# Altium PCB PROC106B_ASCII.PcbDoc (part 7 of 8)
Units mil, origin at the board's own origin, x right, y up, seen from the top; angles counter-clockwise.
Board outline 4498.18 x 1060.53 mil, 8 copper layers (Top Layer, GND1, Sig1, PWR1, PWR2, Sig2, GND2, Bottom Layer), stack 69.602 mil thick; 439 components, 327 nets, 1548 pads, 843 vias.
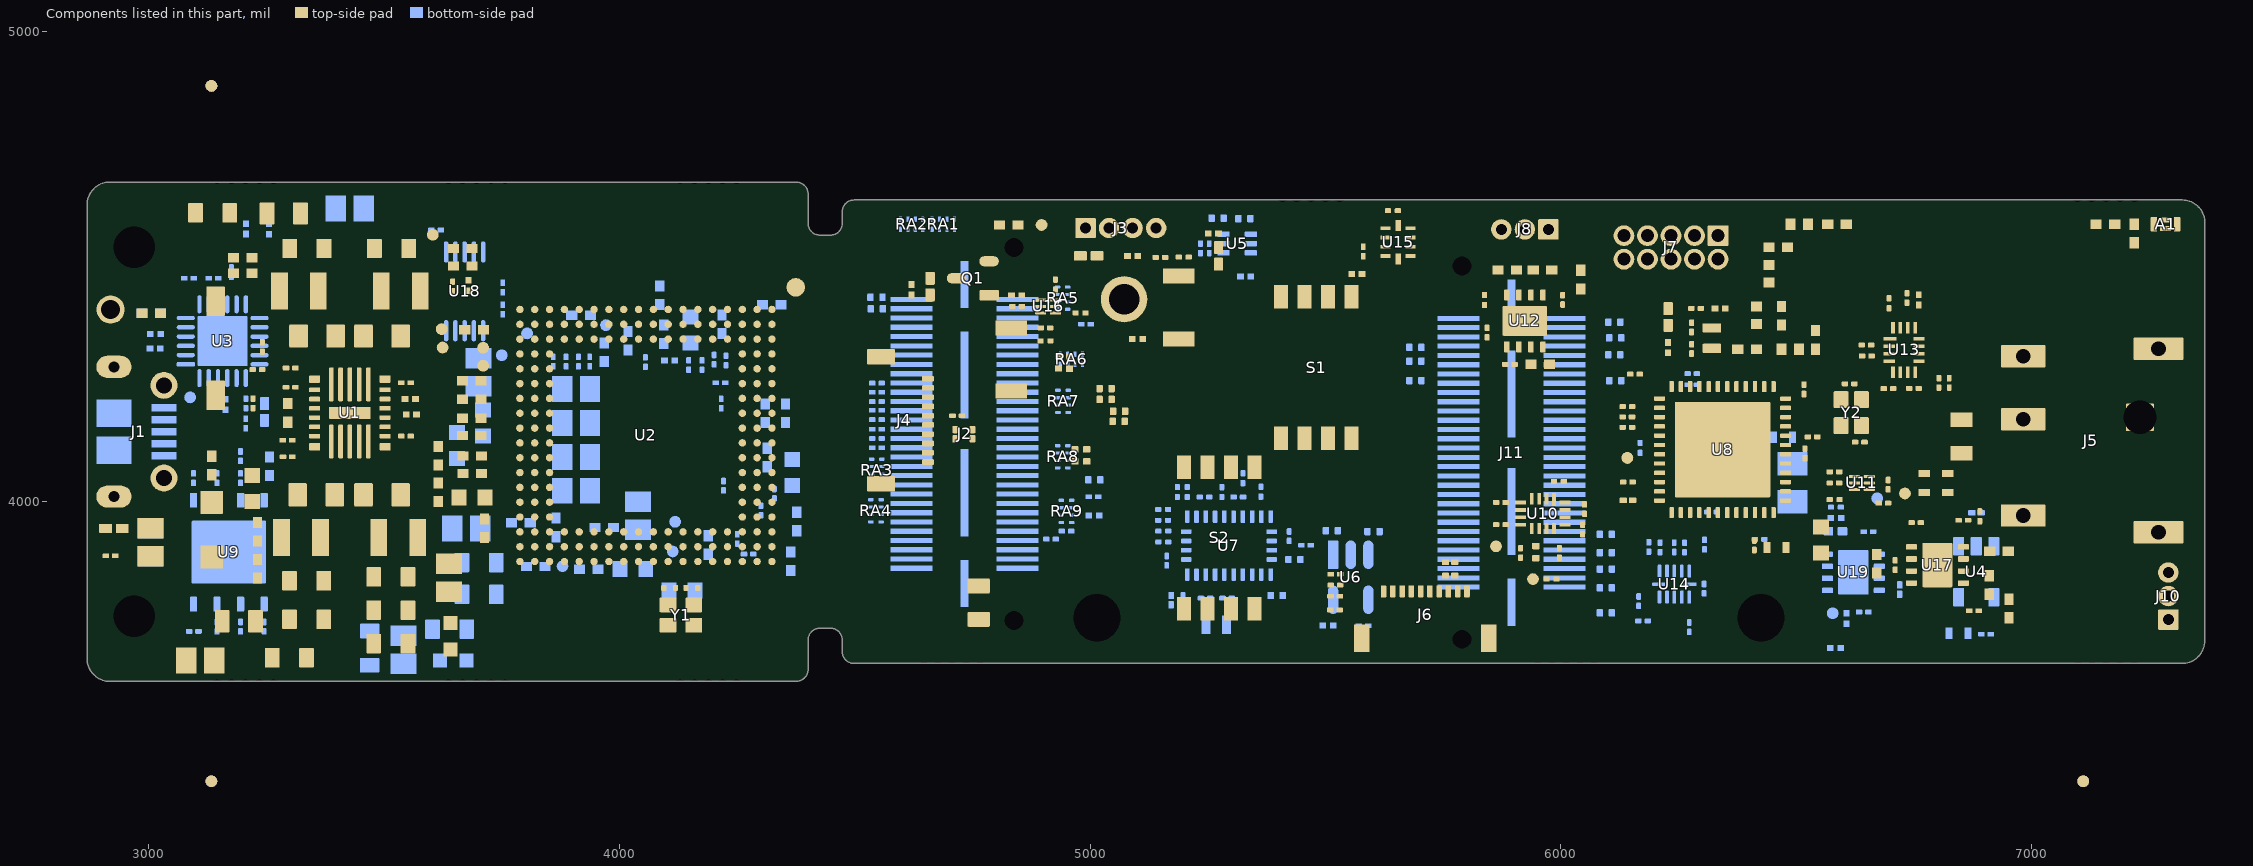
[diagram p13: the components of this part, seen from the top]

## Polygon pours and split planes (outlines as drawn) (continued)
GND on Bottom Layer "Bottom Layer-GND 3" (solid, remove dead copper, pour order 760): 3437.8,4669.84 3522.45,4669.84 3522.45,4586.72 3437.8,4586.72
GND on Bottom Layer "Bottom Layer-GND 5" (solid, remove dead copper, pour order 756): 3589.51,3885.19 3589.51,3816.34 3622.06,3783.79 3660.04,3745.8 3660.04,3708.73 3691.76,3708.73 3691.76,3893.86 3678.45,3907.17 3611.49,3907.17
GND on Bottom Layer "Bottom Layer-GND 2" (solid, remove dead copper, pour order 748): 3921.61,4124.36 3995.34,4124.36 3995.34,3981.19 3921.61,3981.19
AR_1P2 on Bottom Layer "Bottom Layer-AR_1P2" (solid, remove dead copper, pour order 742): 3283.69,4679.43 3417.05,4679.43 3417.05,4582.18 3283.69,4582.18
5V_IN on Bottom Layer "Bottom Layer-5V_IN" (solid, remove dead copper, pour order 721): 2969.58,3908.01 3085.96,3908.01 3085.96,3827.52 2969.58,3827.52
PMIC_1V0 on Bottom Layer "Bottom Layer-PMIC_1V0" (solid, remove dead copper, pour order 719): 3710.58,3701.2 3698.85,3689.47 3661.67,3689.47 3661.67,3629.17 3763.64,3629.17 3763.64,3701.2
no net on Bottom Layer "BOTTOM-No Net 1" (solid, remove dead copper, pour order 709): 3713.85,4118.01
no net on Bottom Layer "BOTTOM-No Net" (solid, pour order 707): 3795.02,4389.29
no net on Bottom Layer " " (solid, remove dead copper, pour order 705): 3587.57,4370.79
no net on Bottom Layer " " (solid, remove dead copper, pour order 703): 3587.57,4370.79
AR_1V8 on Bottom Layer "Bottom Layer-BB_1V8" (solid, remove dead copper, pour order 701): 3903.37,4272.45 3852.76,4272.45 3665,4272.45 3665,4219.16 3815.53,4219.16 3824.69,4210 3903.37,4210
AR_1V8 on Bottom Layer "BOTTOM-VCO_1V8" (solid, remove dead copper, pour order 697): 3975,3962.68 4012.22,3962.68 4071,3962.68 4071,3910.88 3975,3910.88
AR_1P0_RF1 on Bottom Layer "Bottom Layer-AR_1P0_RF1" (solid, remove dead copper, pour order 695): 3856.3,4159.48 3856.3,4197.12 3899.77,4197.12 3900.11,4131.96 3794.33,4131.96 3774.34,4131.96 3764.92,4122.55 3691.55,4122.54 3691.55,4159.48
AR_1V8 on Bottom Layer "BOTTOM-VCLK_1V8" (solid, remove dead copper, pour order 691): 3679.79,3911.04 3910.06,3911.04 3910.06,3943.24 3783.91,3943.24 3783.91,3983.65 3679.79,3983.65
no net on Bottom Layer "Bottom Layer-No Net" (solid, pour order 683): 3057.31,4083.94
PMIC_3V3 on Bottom Layer "Bottom Layer-PMIC_3V3" (solid, remove dead copper, pour order 681): 3004.01,4452.9 3113.51,4452.9 3113.51,4399.78 3109.47,4395.73 3102.51,4395.73 3097.94,4391.16 3097.94,4365.53 3051.98,4365.53 3033.61,4383.9 3004.01,4383.9
AR_1P0_RF1 on Bottom Layer "Bottom Layer-AR_1P0_RF1 1" (solid, remove dead copper, pour order 679): 3715.91,3777.88 3715.91,3726.32 3794.09,3726.32 3794.09,3828.85 3780.86,3842.09 3780.86,3896.41 3715.91,3896.41
5V_HD_IN on Bottom Layer "Bottom Layer-5V_HD_IN 1" (solid, pour order 557): 6641.93,3812.08 6641.93,3696.21 6707.53,3696.21 6707.53,3812.08 6702.57,3812.08 6659.82,3812.08 6662.84,3812.08
5V_HD_IN on Bottom Layer "Bottom Layer-5V_HD_IN 3" (solid, pour order 563): 4868.09,3859.51
5V_IN_B on Bottom Layer "Bottom Layer-5V_IN_B" (solid, pour order 521): 6653.01,3852.6 6759.98,3852.6 6759.98,4006.83 6775.86,4022.71 6798.1,4022.71 6798.1,4150.17 6690.11,4150.17 6690.11,4110.05 6690.85,4109.3 6690.85,4101.69 6690.85,4075.96 6690.86,4067.7 6655.23,4032.07 6655.23,3923.83 6657.56,3921.5 6658.81,3920.25 6675.91,3903.15 6685.85,3893.21 6685.75,3876.47 6681.98,3872.7 6653.01,3872.7
RE on Bottom Layer "Bottom Layer-RE" (solid, remove dead copper, pour order 505): 7331.54,4438.37 7307.92,4438.37 7307.92,4627.35 7331.54,4627.35
5V_IN on Bottom Layer "BOTTOM-5V_IN_SW" (solid, pour order 318): 6716.51,3843.31 6664.37,3843.31 6664.37,3827.48 6697.27,3827.48 6706.84,3817.91 6713.65,3817.91 6727.01,3817.91 6727.01,3728.16 6799.26,3728.16 6826.37,3755.28 6826.37,3800.18 6821.37,3805.18 6801.37,3805.18 6782.49,3805.18 6777.74,3809.92 6777.74,3842.18 6773.37,3846.18 6719.37,3846.18
no net on Bottom Layer " " (solid, remove dead copper, pour order 459): 4514.15,4464.37
no net on Bottom Layer "BOTTOM-No Net 3" (solid, pour order 266): 4918.91,3816.49
no net on Bottom Layer "BOTTOM-No Net 4" (solid, pour order 264): 4983.76,3878.78
AR_1P0_RF1 on PWR1 "PWR1-AR_1P0_RF1" (solid, remove dead copper, pour order 725): 3696.4,3846.98 3714.8,3828.66 3783.45,3828.66 3783.45,3726.14 3520.23,3726.14 3520.23,3982.24 3689.65,4151.66 3872.58,4151.66 3872.58,4038.59 3731.51,4038.59 3696.4,4003.44
AR_1P2 on PWR1 "PWR1-AR_1P2" (solid, remove dead copper, pour order 731): 4383.81,4173.3 4383.81,4319.42 4383.81,4679.43 3769.2,4679.43 3254.72,4679.43 3254.72,4485.55 3606.66,4485.55 3606.66,4349.35 3935.57,4349.35 3935.57,4419.55 4276.95,4419.55 4302.94,4393.56 4302.94,4179.48 4325.05,4157.06 4325.05,4115.19 4335.64,4104.6 4335.64,3889.16 4152.76,3889.16 4152.76,3822.45 4383.81,3822.45 4383.81,4093.23
AR_1V8 on PWR1 "PWR1-AR_1V8" (solid, remove dead copper, pour order 723): 4317.82,4156.75 4296.2,4178.37 4296.2,4372.39 4266.03,4403.13 3952.06,4403.13 3910.52,4361.6 3660.28,4361.6 3593.74,4295.06 3322.56,4294.82 3322.56,3824.21 3281.64,3783.2 3142.74,3783.2 3142.74,3618.01 3500.96,3618.01 3500.96,3997.33 3676.25,4172.62 3923.29,4172.62 3923.29,4273.48 4199.1,4273.48 4199.1,4021.86 4199.1,4020.83 4184.31,4005.54 3744.04,4005.54 3729.16,3990.66 3729.26,3874.14 3749.49,3853.9 3750.27,3853.73 3989.56,3853.73 4046.2,3910.37 4317.82,3910.37
PMIC_1V0 on PWR1 "PWR1-PMIC_1V0" (solid, remove dead copper, pour order 864): 3679.96,3619.99 3679.96,3702.53 3774.68,3702.53 3774.68,3619.99
5V_IN on PWR1 "PWR1-5V_IN 1" (solid, remove dead copper, pour order 804): 6141.87,4641.38 7225.46,4641.38 7225.46,4357.95 7367.49,4358.05 7367.49,3676.33 6736.31,3676.33 6736.31,3926.82 6479.48,4183.28 5319.35,4183.28 4687.15,4183.28 4621.42,4117.56 4621.33,3669.11 4525.19,3669.11 4484.07,3669.11 4484.07,3849.59 4504.63,3849.59 4525.19,3864.58 4525.19,4641.38 5562.04,4641.38
5V_HD_IN on PWR1 "PWR1-5V_HD_IN" (solid, remove dead copper, pour order 366): 4635.53,4107.41 4635.53,3657.14 4801.12,3657.14 6712,3657.14 6712,3928.7 6480.61,4160.09 4688.21,4160.09
GND on PWR1 "PWR1-GND" (solid, remove dead copper, pour order 820): 3962.57,4259.22 3962.51,4259.86 4180.36,4259.86 4180.36,4031.23 3955.54,4031.23 3955.54,4259.22
5V_IN on PWR1 "PWR1-5V_IN" (solid, remove dead copper, pour order 734): 3300,3843.45 3252.31,3795.76 3252.31,3795.43 3073.61,3795.43 3073.61,3588.77 2869.58,3588.77 2869.58,4710.9 3245.35,4710.9 3245.35,4475.15 3587.25,4475.15 3587.25,4312.5 3300,4312.5
no net on PWR1 "L4 PWR/GND-No Net" (solid, pour order 380): 3990.62,4017.94
GND on Sig1 "      " (solid, remove dead copper, pour order 850): 2828.55,3502.51 4359.83,3502.51 4359.83,3540.49 7326.73,3540.49 7326.73,4241.62 7189.18,4241.62 7189.18,4455.67 7189.2,4491.21 7189.18,4525 4359.83,4525 4359.83,4563.04 2828.55,4563.04
GND on Sig1 "      " (solid, pour order 848): 7230.23,4607.59
3V0 on Sig1 "Sig1-3V0" (solid, remove dead copper, pour order 422): 5446.44,3648.08 5446.44,3740.77 5595.34,3889.68 5748.5,3889.68 5802.08,3836.09 5802.08,3784.14 5860.53,3725.69 6169.64,3725.69 6235.53,3789.89 6235.53,3854.82 6235.53,3991.13 6627.54,3991.13 6738.96,3879.71 6738.96,3854.82 6817.4,3854.82 6844.28,3827.94 6844.28,3688.85 6676.2,3688.85 6676.2,3872.61 6372.91,3872.61 6372.91,3648.08
no net on Sig1 "Sig1-No Net" (solid, remove dead copper, pour order 740): 4088.43,4371.99
no net on Sig1 "L3 SIG 1-No Net" (solid, pour order 511): 3904.98,4012.92
GND on GND1 "GND1-GND" (solid, remove dead copper, pour order 358): 4400.86,4641.38 4400.86,4683.33 2896.63,4683.34 2866.42,4653.12 2866.42,3646.93 2901.93,3611.42 2908,3617.49 4400.86,3617.49 4400.86,3656.87 7367.49,3656.87 7367.49,4358 7230.09,4358 7230.25,4641.38
no net on GND1 "L6 SIG 2-No Net" (solid, pour order 302): 4825.92,3926.28
no net on GND1 "DVDD_21MP_1V8_L08_P-001" (solid, remove dead copper, pour order 300): 3885.7,4301.32
PMIC_3V3 on PWR2 "PWR2-PMIC_3V3" (solid, remove dead copper, pour order 487): 4615.73,4308.97 4816.08,4509.31 4816.08,4512.23 4816.08,4631.43 4498.89,4631.43 4400.86,4631.43 4400.86,4710.69 2869.58,4710.9 2869.58,3586.35 4376.76,3586.35 4376.76,3820.05 4376.76,4308.97 4415.39,4308.97
VCC_BA_3V3 on PWR2 "PWR2-VCC_BA_3V3" (solid, remove dead copper, pour order 738): 4794.48,4263.72 4759.59,4298.61 4759.59,4414.21 4838.48,4493.1 4838.48,4641.38 7229.32,4641.38 7229.31,4358 7367.49,4358 7367.49,3657.14 4794.48,3657.14
5V_IN on PWR2 " " (solid, remove dead copper, pour order 485): 3880.16,4286.09 3848.77,4254.7 3706.1,4254.7 3706.1,4223.31 3664.77,4181.97 3492.6,4181.97 3492.6,4313.97 3583.8,4313.97 3584.11,4493.43 3259.65,4493.43 3259.65,3889.51 4016.31,3889.51 4108.84,3982.04 4306.6,3982.03 4322,3966.64 4322,3920.77 4353.26,3889.51 4413.43,3889.51 4439.46,3863.48 4453.67,3863 4483.91,3863 4485.31,3861.61 4485.31,3661.8 4490.12,3656.98 4514.15,3656.87 4748.59,3656.87 4748.59,3887.85 4748.59,4286.09
VDDS on PWR2 "PWR2-VDDS" (solid, remove dead copper, pour order 404): 6492.17,3939.96 6492.17,4039.29 6539.41,4086.52 6582.96,4086.52 6582.96,4179.9 6582.31,4179.25 6460.14,4179.25 6427.22,4212.17 6283.81,4212.17 6200.92,4295.06 6134.69,4295.06 6134.69,4010.53 6208.12,3939.96
no net on PWR2 " " (solid, remove dead copper, pour order 406): 3419.66,3877.85
no net on Bottom Solder (solid): 4400.86,4518.08 3736.09,4518.08 3736.09,4678.67 4400.86,4678.67
no net on Bottom Solder (solid): 3815.62,3618.33 3815.62,3780.33 4400.86,3780.33 4400.86,3634.41 4384.78,3618.33
no net on Bottom Solder (solid): 4189.03,4266.74 4189.03,4031.3 4008.5,4031.3 4008.5,4266.74
no net on Bottom Solder " " (solid, remove dead copper): 4514.15,4464.37
no net on Bottom Solder " " (solid, remove dead copper): 4512,4464.37
no net on M1 Board Outline " " (solid, remove dead copper): 3143.52,4361.87
no net on M1 Board Outline " " (solid, remove dead copper): 3145.55,4361.06
no net on Top Paste " " (solid): 4029.26,4016.78 3910.77,4016.78 3910.77,4130.21 4029.26,4130.21
no net on Top Paste " " (solid): 4169.12,4155.98 4050.63,4155.98 4050.63,4269.41 4169.12,4269.41
no net on Top Paste " " (solid): 4169.12,4016.78 4050.63,4016.78 4050.63,4130.21 4169.12,4130.21
no net on Top Paste " " (solid): 4029.26,4155.98 3910.77,4155.98 3910.77,4269.41 4029.26,4269.41
no net on Top Solder " " (solid): 4169.12,4016.78 4050.63,4016.78 4050.63,4130.21 4169.12,4130.21
no net on Top Solder " " (solid): 4169.12,4155.98 4050.63,4155.98 4050.63,4269.41 4169.12,4269.41
no net on Top Solder " " (solid): 4029.26,4016.78 3910.77,4016.78 3910.77,4130.21 4029.26,4130.21
no net on Top Solder " " (solid): 4029.26,4155.98 3910.77,4155.98 3910.77,4269.41 4029.26,4269.41
GND on GND2 "GND 3-GND" (solid, remove dead copper, pour order 310): 4438.86,3618.9 7367.49,3614.6 7367.49,4358 7230.24,4358 7230.24,4686.41 4522.77,4686.41 2869.56,4686.41 2869.85,3618.9
GND on Sig2 "      " (solid, remove dead copper, pour order 854): 2869.58,3618.9 4400.86,3618.9 4400.86,3656.87 4400.86,3731.52 4473.63,3731.52 4473.63,3657.18 4474.07,3656.87 7367.49,3656.87 7367.49,4358 7228.97,4358 7228.97,4572.06 7228.97,4607.59 7228.97,4641.38 4400.86,4641.38 4400.86,4679.43 2869.58,4679.43

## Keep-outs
Bottom Layer:
  rectangle: 3813.97,3824.21 4076.76,3834.25
Keep-Out Layer:
  circle w1: c5014.62,3754.06 r118.11
  circle w1: c6425.96,3754.06 r118.11
  text ".Layer_Name" at 577,-858.49 h60

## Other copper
Top Layer:
  text ".Layer_Name" at 577,-858.49 h60
GND1:
  text ".Layer_Name" at 577,-858.49 h60
Sig1:
  text ".Layer_Name" at 577,-858.49 h60
PWR1:
  text ".Layer_Name" at 577,-858.49 h60
PWR2:
  text ".Layer_Name" at 577,-858.49 h60
Sig2:
  text ".Layer_Name" at 577,-858.49 h60
GND2:
  text ".Layer_Name" at 577,-858.49 h60
Bottom Layer:
  text ".Layer_Name" at 577,-858.49 h60

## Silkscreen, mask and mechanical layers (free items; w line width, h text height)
Top Overlay:
  drawing of 931 lines, arcs and shapes, not listed
  text "ANT" at 7247.11,4618.46 h15
  text "3V3" at 4971.03,4609.77 h15
  text "SCL" at 5026.44,4609.1 h15
  text "SDA" at 5075.13,4609.42 h15
  text "GND" at 5132,4609 h15
  text "CAN1" at 5705.55,4605.09 h15
  text "3V3" at 3575.93,4600.61 h15
  text "CAN_L" at 6013.93,4563.4 h15
  text "CAN_H" at 5772.29,4557.35 h15
  text "GND" at 5902.73,4526.81 h15
  text "60PIN" at 5461.3,4505.87 h15 r90
  text "60PIN/BT" at 5407.96,4487.66 h15 r90
  text "3V3" at 4942.95,4473.45 h15
  text "LED" at 4995.38,4473.19 h15
  text "BT_JTAG_HDR" at 6201.8,4466.71 h15
  text "USR_LED" at 5256.55,4450.34 h13
  text "PROC106B" at 6836.63,4404.24 h25
  text "RST_LED" at 4614,4391 h15
  text "REV. B" at 6899.9,4369.83 h25
  text "GND" at 5054.02,4359.61 h15
  text "GND" at 2907.55,4353.02 h15
  text "BT_LED" at 6186.99,4348.24 h15 r90
  text "S3" at 3013.35,4323.17 h25
  text "USR_SW" at 5152.14,4301.5 h15
  text "SOP2" at 2999.29,4296.66 h15
  text "RST_SW" at 4794.22,4190.93 h15
  text "CAN" at 5202.96,4125.61 h15 r90
  text "60PIN" at 5257.16,4116.94 h15 r90
  text "BT_EN" at 5300.52,4106.1 h15 r90
  text "PROC106B" at 2866.22,4100.51 h25
  text "REV. B" at 2897.63,4071.86 h25
  text "BT" at 5464.69,4051.28 h15 r90
  text "SOP0" at 5511.87,4024.99 h15 r90
  text "SOP1" at 5563.64,4022.15 h15 r90
  text "CP2105" at 5431.33,4007.09 h15 r90
  text "5V_LED" at 2974.55,3984.77 h15
  text "LCD_DISP2" at 4737,3978 h15 r90
  text "5V, 2A" at 7023.94,3880.64 h25
  text "CAN_H" at 7195.3,3876.22 h15
  text "LCD_DISP1" at 5564.31,3865.44 h15
  text "GND" at 7243.19,3786.08 h15 r90
  text "CAN2" at 7119,3761 h25
  text "CAN_L" at 7189,3721 h15
  text "BT_DIS" at 5331.39,3700.83 h15
  text "BT/LCD" at 5214.43,3697.87 h15
  text "SPI" at 5198.89,3696.39 h15 r90
  text ".Layer_Name" at 557.88,-855.15 h60
Bottom Overlay:
  lines w6: 3076.75,4275.09 3064.53,4275.09 3077.44,4262.17 3077.44,4274.39 ; 3742.27,4351.32 3750.91,4342.68 3750.91,4360.94 3742.27,4352.3 ; 4566.51,3859.44 4557.87,3850.8 4557.87,3869.06 4566.51,3860.42 ; 5190.34,3835.05 5178.12,3835.05 5191.04,3822.14 5191.04,3834.36 ; 5366.68,4568.32 5375.32,4559.68 5375.32,4577.94 5366.68,4569.3 ; 5498.49,3885.48 5489.85,3876.84 5489.85,3895.1 5498.49,3886.46 ; 6061.18,4387.35 6069.82,4378.71 6069.82,4396.98 6061.18,4388.34 ; 6286.44,3772.48 6277.8,3763.84 6296.07,3763.84 6287.43,3772.48 ; 6545.92,3811.92 6537.28,3803.28 6537.28,3821.55 6545.92,3812.91 ; 6822.27,3908.34 6813.62,3899.69 6813.62,3917.96 6822.27,3909.32
  lines w7.64: 3376.95,4259.36 3435.38,4360.56 3493.81,4259.36 3376.95,4259.36
  text "S/N:" at 7054.26,4555.33 h40
  text "J11" at 5720.69,4441.63 h25
  text "OPN:" at 7053.04,4398.05 h40
  text "For evaluation only;" at 6904.33,4270.31 h30
  text "not FCC approved for resale." at 6905.33,4220.31 h30
  text "USB_LED" at 3294.77,4133.76 h15 r270
  text "ICBOOST_CONN" at 5046.93,4070.06 h25 r270
  text "DCA_CONN" at 5658.79,4014.25 h25 r270
  text "USB1" at 2938.13,3956.53 h15
  text "U14" at 6365,3859 h25
  text ".Layer_Name" at 577,-858.49 h60
Top Paste:
  text ".Layer_Name" at 577,-858.49 h60
Bottom Paste:
  text ".Layer_Name" at 577,-858.49 h60
Top Solder:
  text ".Layer_Name" at 577,-858.49 h60
  text ".Layer_Name" at 577,-858.49 h60
Bottom Solder:
  text ".Layer_Name" at 577,-858.49 h60
Drill Guide:
  text ".Layer_Name" at 577,-858.49 h60
M1 Board Outline:
  lines w1: 2917.58,3586.87 2917.58,3586.87
  lines w6: 3043.52,4771.95 2893.99,4771.95 ; 4408.74,4993.07 7334.57,4993.07 ; 5242.82,4819.03 cw(c5242.82,4776.51) 5285.34,4776.51 ccw(c5327.85,4776.51) 5327.85,4734 5349.85,4734 ; 5242.82,4819.16 4924.89,4819.16 ccw(c4924.89,4776.65) 4882.38,4776.65 cw(c4839.86,4776.65) 4839.86,4734.13 4405.8,4734.13 cw(c4405.8,4743.59) 4396.34,4743.59 4396.34,4758.92 ccw(c4383.31,4758.92) 4383.31,4771.95 2893.99,4771.95 ; 5631,4734 5670.37,4734 ccw(c5670.37,4776.51) 5712.88,4776.51 cw(c5755.4,4776.51) 5755.4,4819.03 cw(c5755.57,4819.03) 5755.57,4819.2 6393.01,4819.2 cw(c6393.01,4776.68) 6435.53,4776.68 ccw(c6478.04,4776.68) 6478.04,4734.17 ; 6478.04,4733.95 7319.76,4733.95 ccw(c7319.57,4733.95) 7319.57,4734.13 7320.05,4734.13 ; 6824.41,4993.07 2895.02,4993.07 ccw(c2895.02,4967.63) 2869.59,4967.63 2869.59,4796.35 ccw(c2893.99,4796.35) 2893.99,4771.95 ; 7317.76,4993.07 cw(c7317.76,4943.07) 7367.76,4943.07 7367.76,4781.58 cw(c7320.31,4781.58) 7320.31,4734.13 ; 7320.59,3563.53 4607.03,3563.53 4428.96,3563.53 ccw(c4428.96,3550.55) 4415.97,3550.55 4415.97,3537.53 cw(c4404.81,3537.53) 4404.81,3526.38 3043.52,3526.38 2923.72,3526.38 2907.56,3526.38 ccw(c2907.56,3488.4) 2869.58,3488.4 2869.58,3349.31 ccw(c2912.09,3349.31) 2912.09,3306.8 6841.48,3306.8 7329.95,3306.8 ccw(c7329.95,3343.5) 7366.66,3343.5 ; 7321.69,3563.53 cw(c7321.69,3517.44) 7367.79,3517.44 ; 7367.76,3343.5 7367.76,3517.41
  lines w10: 2869.58,3666.9 ccw(c2917.58,3666.9) 2917.58,3618.9 ; 2869.58,3666.9 ccw(c2917.58,3666.9) 2917.58,3618.9 ; 2869.58,3666.9 2869.58,4631.43 ; 2869.58,3666.9 2869.58,4631.43 ; 2869.58,4631.43 cw(c2917.58,4631.43) 2917.58,4679.43 ; 2869.58,4631.43 cw(c2917.58,4631.43) 2917.58,4679.43 ; 2917.58,3618.9 4375.86,3618.9 2917.58,3618.9 ; 2917.58,4679.43 4375.28,4679.43 2917.58,4679.43 ; 4400.86,3644 cw(c4375.86,3644) 4375.86,3619 ccw(c4375.86,3644) 4400.86,3644 ; 4400.86,3644 4400.86,3706.52 ; 4400.86,3644 4400.86,3706.52 ; 4400.86,3706.52 cw(c4425.86,3706.52) 4425.86,3731.52 ; 4400.86,3706.52 cw(c4425.86,3706.52) 4425.86,3731.52 ; 4400.86,3876.17 ccw(c4425.86,3876.17) 4425.86,3851.17 ; 4400.86,3876.17 ccw(c4425.86,3876.17) 4425.86,3851.17 ; 4400.86,3876.17 4400.86,3900.82 ; 4400.86,3876.17 4400.86,3900.82 ; 4400.86,3900.82 cw(c4425.86,3900.82) 4425.86,3925.82 ; 4400.86,3900.82 cw(c4425.86,3900.82) 4425.86,3925.82 ; 4400.86,4136.81 ccw(c4425.86,4136.81) 4425.86,4111.81 ; 4400.86,4136.81 ccw(c4425.86,4136.81) 4425.86,4111.81 ; 4400.86,4136.81 4400.86,4161.47 ; 4400.86,4136.81 4400.86,4161.47 ; 4400.86,4161.47 cw(c4425.86,4161.47) 4425.86,4186.47 ; 4400.86,4161.47 cw(c4425.86,4161.47) 4425.86,4186.47 ; 4400.86,4397.47 ccw(c4425.86,4397.47) 4425.86,4372.47 ; 4400.86,4397.47 ccw(c4425.86,4397.47) 4425.86,4372.47 ; 4400.86,4397.47 4400.86,4422.12 ; 4400.86,4397.47 4400.86,4422.12 ; 4400.86,4422.12 cw(c4425.86,4422.12) 4425.86,4447.12 ; 4400.86,4422.12 cw(c4425.86,4422.12) 4425.86,4447.12 ; 4400.86,4591.77 ccw(c4425.86,4591.77) 4425.86,4566.77 ; 4400.86,4591.77 ccw(c4425.86,4591.77) 4425.86,4566.77 ; 4400.86,4591.77 4400.86,4654.3 ; 4400.86,4591.77 4400.86,4654.3 ; 4400.86,4654.3 ccw(c4375.86,4654.3) 4375.86,4679.3 cw(c4375.86,4654.3) 4400.86,4654.3 ; 4425.86,3731.52 4448.63,3731.52 ; 4425.86,3731.52 4448.63,3731.52 ; 4425.86,3851.17 4448.63,3851.17 ; 4425.86,3851.17 4448.63,3851.17 ; 4425.86,3925.82 4448.63,3925.82 ; 4425.86,3925.82 4448.63,3925.82 ; 4425.86,4111.81 4448.63,4111.81 ; 4425.86,4111.81 4448.63,4111.81 ; 4425.86,4186.47 4448.63,4186.47 ; 4425.86,4186.47 4448.63,4186.47 ; 4425.86,4372.47 4448.63,4372.47 ; 4425.86,4372.47 4448.63,4372.47 ; 4425.86,4447.12 4448.63,4447.12 ; 4425.86,4447.12 4448.63,4447.12 ; 4425.86,4566.77 4448.63,4566.77 ; 4425.86,4566.77 4448.63,4566.77 ; 4448.63,3731.52 cw(c4448.63,3706.52) 4473.63,3706.52 ; 4448.63,3731.52 cw(c4448.63,3706.52) 4473.63,3706.52 ; 4448.63,3851.17 ccw(c4448.63,3876.17) 4473.63,3876.17 ; 4448.63,3851.17 ccw(c4448.63,3876.17) 4473.63,3876.17 ; 4448.63,3925.82 cw(c4448.63,3900.82) 4473.63,3900.82 ; 4448.63,3925.82 cw(c4448.63,3900.82) 4473.63,3900.82 ; 4448.63,4111.81 ccw(c4448.63,4136.81) 4473.63,4136.81 ; 4448.63,4111.81 ccw(c4448.63,4136.81) 4473.63,4136.81 ; 4448.63,4186.47 cw(c4448.63,4161.47) 4473.63,4161.47 ; 4448.63,4186.47 cw(c4448.63,4161.47) 4473.63,4161.47 ; 4448.63,4372.47 ccw(c4448.63,4397.47) 4473.63,4397.47 ; 4448.63,4372.47 ccw(c4448.63,4397.47) 4473.63,4397.47 ; 4448.63,4447.12 cw(c4448.63,4422.12) 4473.63,4422.12 ; 4448.63,4447.12 cw(c4448.63,4422.12) 4473.63,4422.12 ; 4448.63,4566.77 ccw(c4448.63,4591.77) 4473.63,4591.77 ; 4448.63,4566.77 ccw(c4448.63,4591.77) 4473.63,4591.77 ; 4473.47,4616.39 cw(c4498.47,4616.39) 4498.47,4641.39 ccw(c4498.47,4616.39) 4473.47,4616.39 ; 4473.47,4616.39 4473.63,4591.77 ; 4473.47,4616.39 4473.63,4591.77 ; 4473.63,3706.52 4473.63,3681.91 4473.63,3706.52 ; 4473.63,3876.17 4473.63,3900.82 ; 4473.63,3876.17 4473.63,3900.82 ; 4473.63,4136.81 4473.63,4161.47 ; 4473.63,4136.81 4473.63,4161.47 ; 4473.63,4397.47 4473.63,4422.12 ; 4473.63,4397.47 4473.63,4422.12 ; 7319.76,4641.43 cw(c7319.76,4593.44) 7367.75,4593.44 ; 7319.76,4641.43 cw(c7319.76,4593.44) 7367.75,4593.44 ; 7319.76,4641.43 4498.47,4641.43 7319.76,4641.43 ; 7367.76,3704.87 cw(c7319.76,3704.87) 7319.76,3656.87 ccw(c7319.76,3704.87) 7367.76,3704.87 ; 7367.76,3704.87 7367.76,4593.44 ; 7367.76,3704.87 7367.76,4593.44 ; 7367.75,4593.44 7367.76,4593.44 ; 7367.75,4593.44 7367.76,4593.44 ; 4473.47,3681.91 ccw(c4498.47,3681.91) 4498.47,3656.91 cw(c4498.47,3681.91) 4473.47,3681.91 ; 4498.47,3656.87 7319.49,3656.87 4498.47,3656.87
  text "M1 Board Outline" at 577,-858.49 h60
M2 Board Dimensions:
  text "X3" at 4305,3996 h60 r90
  text "X3" at 4837,3440 h60
  text "M2 Board Dimensions" at 577,-858.49 h60
M3 3D STEP Top:
  text ".Layer_Name" at 577,-858.49 h60
M4 3D STEP Bottom:
  text ".Layer_Name" at 577,-858.49 h60
M5 Assembly Top:
  lines w2: 3900.18,4006.48 3900.18,4279.71 4179.71,4279.71 4179.71,4006.48 3900.18,4006.48
  lines w6: 3737.37,3862.55 3745.19,3854.73 3745.92,3854.73 ; 3745.92,4221.46 3745.92,3854.73 ; 3752.8,3861.61 3745.92,3854.73 ; 4662.01,4263.83 4670.65,4255.19 4670.65,4273.46 4662.01,4264.82 4662.01,4263.83 ; 4783.42,4428.97 4783.42,4429.96 4792.06,4438.6 4792.06,4420.33 4783.42,4428.97 ; 4938.22,4398.63 4938.22,4399.62 4946.86,4408.26 4946.86,4389.99 4938.22,4398.63 ; 5551.38,3777.7 5560.02,3786.34 5560.02,3787.32 5551.38,3795.97 5551.38,3777.7 ; 5966.42,4578.64 5975.06,4587.28 5976.04,4587.28 5984.68,4578.64 5966.42,4578.64 ; 6328.53,4574.58 6337.17,4583.22 6338.16,4583.22 6346.8,4574.58 6328.53,4574.58 ; 7291.94,3711.22 7291.94,3729.48 7300.58,3720.84 7300.58,3719.86 7291.94,3711.22
  lines w10: -287.5,-917.17 6312.5,-917.17 ; -287.5,-713.83 6314.5,-713.83 ; -287.5,-510.5 -287.5,-1120.5 3717.5,-1120.5 6314.5,-1120.5 6314.5,-510.5 -287,-510.5 -287,-1120.5 1288.5,-1120.5 ; 2177.5,-1120.5 2177.5,-510.5 ; 3444.5,-713.83 3444.5,-510.5 ; 4284.5,-713.83 4284.5,-510.5 ; 4906.5,-1127 4906.5,-924.17
  text "COMPONENTS MARKED 'DNP' SHOULD NOT BE POPULATED." at -159.85,-299.74 h60
  text "ASSEMBLY VARIANT:" at -160.35,-415.24 h60
  text ".VariantName" at 875.65,-415.24 h60
  text "PCB VIEWED FROM TOP SIDE" at -228.5,-655.67 h60
  text "BOARD #:" at 2248,-655.67 h60
  text ".PRJ_Number" at 2793.5,-655.67 h60
  text "REV:" at 3638,-655.67 h60
  text ".PCB_Rev" at 3929.5,-655.67 h60
  text "SVN REV:" at 4476,-655.67 h60
  text ".VersionControl_RevNumber" at 4982,-655.67 h60
  text ".Layer_Name" at 538.89,-854.26 h60
  text "TID #:" at 2248,-859 h60
  text ".TID" at 2793.5,-859 h60
  text "PLOT NAME =" at -228.5,-1064.34 h60
  text ".plot_File_Name" at 577,-1064.34 h60
  text "GENERATED    :" at 2250,-1064.34 h60
  text ".Print_Date" at 3119.5,-1064.34 h60
  text ".Print_Time" at 3848.5,-1064.34 h60
  text "TEXAS INSTRUMENTS" at 5113,-1064.34 h60
M6 Assembly Bottom:
  lines w6: 3051.59,4095.56 3060.23,4086.92 3060.23,4105.18 3051.59,4096.54 ; 3056.52,4289.78 3047.88,4281.14 3047.88,4299.4 3056.52,4290.76 ; 4556.9,3856.76 4548.26,3848.12 4548.26,3866.39 4556.9,3857.74 ; 6054.41,4389.59 6063.05,4380.95 6063.05,4399.22 6054.41,4390.57
  lines w10: -288,-714.33 6314,-714.33 ; -286,-917.67 6314,-917.67 ; 1120,-1127.5 1120,-924.67 ; 1742,-714.33 1742,-511 ; 2582,-714.33 2582,-511 ; 3849,-1121 3849,-511 ; 4510.26,4292.38 4510.26,4160.86 ; 4518.19,4168.91 4510.26,4160.98 4510.26,4160.86 ; 4738,-1121 6313.5,-1121 6313.5,-511 -288,-511 -288,-1121 2309,-1121 6314,-1121 6314,-511 ; 4510.26,4160.86 4501.64,4169.48 4510.26,4160.86
  text "COMPONENTS MARKED 'DNP' SHOULD NOT BE POPULATED." at 6102,-318 h60
  text ".VariantName" at 5058,-434 h60
  text "ASSEMBLY VARIANT:" at 6097,-434 h60
  text ".VersionControl_RevNumber" at 1035.5,-656.17 h60
  text "SVN REV:" at 1541.5,-656.17 h60
  text ".PCB_Rev" at 2088,-656.17 h60
  text "REV:" at 2379.5,-656.17 h60
  text ".PRJ_Number" at 3224,-656.17 h60
  text "BOARD #:" at 3769.5,-656.17 h60
  text "PCB VIEWED FROM BOTTOM SIDE" at 6246,-656.17 h60
  text ".Layer_Name" at 1514.22,-848.89 h60
  text ".TID" at 3224,-859.5 h60
  text "TID #:" at 3769.5,-859.5 h60
  text "TEXAS INSTRUMENTS" at 904.5,-1064.84 h60
  text ".Print_Time" at 2169,-1064.84 h60
  text ".Print_Date" at 2898,-1064.84 h60
  text "GENERATED    :" at 3767.5,-1064.84 h60
  text ".plot_File_Name" at 5440.5,-1064.84 h60
  text "PLOT NAME =" at 6246,-1064.84 h60
M10 Fab Notes:
  drawing of 254 lines, arcs and shapes, not listed
  text "2" at 3215,8061 h70
  text "1" at 739.84,8036.5 h70
  text "3" at 5724.84,8036.5 h70
  text "4" at 8231.51,8036.5 h70
  text "5" at 10730.5,8036.5 h70
  text "6" at 13235.5,8036.5 h70
  text "A" at -416.5,6893.5 h70
  text "A" at 14383.5,6893.5 h70
  text "DESIGN INFORMATION" at 12391.15,6364.21 h60
  text "4" at 12769.13,6238.04 h60
  text "MIN. TRACK WIDTH:" at 11746.59,6232.09 h60
  text "MIL" at 12997.59,6232.09 h60
  text "MIN. CLEARANCE:" at 11746.59,6107.96 h60
  text "4" at 12782.83,6107.96 h60
  text "MIL" at 12997.59,6107.96 h60
  text "MIN. VIA PAD SIZE:" at 11746.59,5983.83 h60
  text "18" at 12812.84,5983.84 h60
  text "MIL" at 12997.59,5983.83 h60
  text "0.05mm (2MIL)" at 12441.59,5853.93 h60
  text "MINIMUM ANNULAR RING" at 11417.36,5845.71 h60
  text "EXTERNAL" at 13149.59,5845.71 h60
  text "PER" at 11617.36,5735.58 h60
  text "IPC-D-275 CLASS 2 LEVEL C" at 11837.36,5735.58 h60
  text "MIL, HOLES" at 13325.59,5635.11 h60
  text "+/-" at 12933.13,5626.52 h60
  text "+/-" at 13787.13,5626.52 h60
  text "REGISTRATION TOLERANCES:" at 11417.36,5625.46 h60
  text "METAL" at 12617.13,5625.46 h60
  text "5" at 13193.33,5625.46 h60
  text "3" at 14026.33,5625.46 h60
  text "MIL" at 14142.59,5625.46 h60
  text "HOLE SIZE TOLERANCE (UNLESS OTHERWISE SPECIFIED):" at 11417.36,5527.14 h60
  text "+/-" at 13787.13,5524.27 h60
  text "3" at 14026.33,5523.21 h60
  text "MIL" at 14142.59,5523.2 h60
  text "MATERIAL:" at 11342.59,5385.56 h60
  text "FR-4 High Tg" at 12329.03,5257.03 h60
  text "X" at 12176.59,5254.04 h60
  text "FR-408" at 11763.59,5244.53 h60
  text "OTHER" at 13251.59,5244.53 h60
  text "74 MIL (1.86mm) +/-10%" at 12083.69,5101.5 h60
  text "X" at 11963.59,5099.04 h60
  text "THICKNESS:" at 11417.36,5093.27 h60
  text "OTHER" at 13368.59,5093.27 h60
  text "TOLERANCE:" at 11417.36,4954.96 h60
  text "X" at 12265.59,4954.96 h60
  text "ANSI IPC-6012 TYPE 3 CLASS 2" at 12443.6,4954.96 h60
  text "OTHER +/-" at 12443.59,4810.77 h60
  text "BOW & TWIST:" at 11417.36,4665.58 h60
  text "X" at 12265.59,4665.58 h60
  text "ANSI IPC-6012 TYPE 3 CLASS 2" at 12443.6,4665.58 h60
  text "OTHER +/-" at 12443.59,4518.89 h60
  text "B" at -416.5,4513.5 h70
  text "B" at 14383.5,4513.5 h70
  text "DRILLING:" at 11342.59,4388.27 h60
  text "NC_DRILL FILES" at 13103.59,4283.08 h60
  text "REFERENCE:" at 11417.36,4279.14 h60
  text "X" at 12074.59,4279.04 h60
  text "AS SHOWN" at 12252.59,4279.14 h60
  text "X" at 12975.59,4279.14 h60
  text "OTHER" at 13401.59,4136.89 h60
  text "PTH COPPER THICKNESS:" at 11417.03,4133.36 h60
  text "X" at 12556.27,4133.36 h60
  text "20-30 um" at 12684.27,4133.36 h60
  text "BOARD FINISH:" at 11342.59,3985.76 h60
  text "SILKSCREEN:" at 11497.81,3875.64 h60
  text "X" at 12455.59,3875.64 h60
  text "TOP" at 12572.59,3875.64 h60
  text "X" at 12965.59,3875.64 h60
  text "BOTTOM" at 13083.59,3875.64 h60
  text "SILKSCREEN COLOR:" at 11497.81,3720.45 h60
  text "X" at 12454.59,3720.45 h60
  text "WHITE" at 12572.59,3720.45 h60
  text "OTHER" at 13083.59,3720.45 h60
  text "X" at 12585.59,3577 h60
  text "RED" at 12703.59,3577 h60
  text "OTHER" at 13321.59,3577 h60
  text "SOLDER RESIST COLOR:" at 11497.81,3570.13 h60
  text "X" at 12585.59,3422.75 h60
  text "MATTE" at 12703.59,3422.75 h60
  text "SEMI-GLOSS" at 13321.13,3422.11 h60
  text "IMMERSION GOLD (ENIG)" at 12403.59,3249.98 h60
  text "ENEPIG" at 13741.13,3242.75 h60
  text "SURFACE FINISH:" at 11342.59,3241.75 h60
  text "X" at 12225.59,3241.75 h60
  text "IMM. TIN/SILVER OR EQUIV" at 11672.13,3104.44 h60
  text "OTHER" at 13103.59,3100.5 h60
  text "ARRAY/PANEL:" at 11342.59,2945.12 h60
  text "CUT AND TRIM PER M1 BOARD OUTLINE" at 12403.59,2936.9 h60
  text "X" at 12215,2804 h60
  text "N.C. ROUTE" at 12403.59,2800.94 h60
  text "V. SCORE" at 13269.59,2800.94 h60
  text "CERTIFICATION:" at 11342.59,2671.81 h60
  text "MATERIALS AND WORKMANSHIP FOR ALL PCBS" at 12067.59,2671.81 h60
  text "TO MEET OR EXCEED THE REQUIREMENTS OF:" at 12067.59,2577.75 h60
  text "X" at 11705.1,2449.12 h60
  text "ANSI IPC-A-600F CLASS ->" at 11833.09,2449.12 h60
  text "X" at 13481.1,2449.12 h60
  text "2" at 13591.09,2449.12 h60
  text "1" at 13276.09,2447.62 h60
  text "3" at 13945.09,2447.62 h60
  text "X" at 12517.1,2301.43 h60
  text "RoHS" at 12645.09,2301.43 h60
  text "OTHER" at 13289.49,2301.43 h60
  text "PER ORDER" at 13686.55,2301.43 h60
  text "ALL BOARDS MUST MEET OR EXCEED UL94-V0 REQUIREMENTS." at 11370.13,2147.6 h60
  text "C" at -416.5,2138.5 h70
  text "C" at 14383.5,2138.5 h70
  text "PCB MUST BEAR THE UL94V-0 UL REGISTERED MATERIAL ID NUMBER" at 11370.13,2031.54 h60
  text "ADDITIONAL REQUIREMENTS:" at 11342.59,1862.12 h60
  text "MICROSECTION:" at 11417.36,1754.99 h60
  text "YES" at 12323.09,1754.99 h60
  text "REQUIRED" at 13184.59,1610.66 h60
  text "BARE BOARD ELEC. TEST:" at 11417.36,1607.8 h60
  text "NONE" at 12723.09,1607.8 h60
  text "X" at 13066.59,1607.8 h60
  text "PER ORDER" at 13776.59,1607.8 h60
  text "IMPEDANCE SPECIFICATIONS" at 3824.73,1597.91 h82.24
  text "IMPEDANCE SPECIFICATIONS" at 3824.73,1597.91 h82.24
  text "XX MIL VIAS REQUIRE NON-CONDUCTIVE FILL AND PLANARIZE" at 11585.51,1402.85 h59
  text "SL#" at 3713.7,1310.07 h82.24
  text "SL#" at 3713.7,1310.07 h82.24
  text "TYPE" at 4852.75,1310.07 h82.24
  text "TYPE" at 4852.75,1310.07 h82.24
  text "LAYER" at 6053.48,1310.07 h82.24
  text "LAYER" at 6053.48,1310.07 h82.24
  text "TRACEWIDTH(Mils)" at 6740.2,1310.07 h82.24
  text "TRACEWIDTH(Mils)" at 6740.2,1310.07 h82.24
  text "SPACING(Mils)" at 8093.08,1310.07 h82.24
  text "SPACING(Mils)" at 8093.08,1310.07 h82.24
  text "IMPEDANCE(Ohms)" at 9240.36,1310.07 h82.24
  text "IMPEDANCE(Ohms)" at 9240.36,1310.07 h82.24
  text "REF LAYER" at 10506.88,1310.07 h82.24
  text "REF LAYER" at 10506.88,1310.07 h82.24
  text "XX MIL VIAS REQUIRE CONDUCTIVE FILL AND PLANARIZE" at 11593.51,1298.88 h60
  text "X" at 11460.14,1142.4 h60
  text "OUTER XX MIL TRACES REQUIRE 50 OHM SINGLE-ENDED IMPEDANCE" at 11592.52,1135.49 h58
  text "L02,L07" at 10662.95,1128.02 h82.24
  text "L1,L8" at 6083.27,1124.91 h82.24
  text "6.7" at 7231.18,1121.73 h82.24
  text "---" at 8485.37,1121.73 h82.24
  text "50" at 9698.44,1121.73 h82.24
  text "MICROSTRIP" at 4032.46,1112.2 h82.24
  text "01" at 3746.6,1104.46 h82.24
  text "01" at 3746.6,1104.46 h82.24
  text "L07" at 10663.5,988.62 h82.24
  text "5" at 8544.58,985.21 h82.24
  text "L8" at 6083.27,980.99 h82.24
  text "X" at 11462.02,980.86 h60
  text "EDGE COUPLED MICROSTRIP" at 4033.7,980.4 h82.24
  text "5" at 7231.18,977.81 h82.24
  text "90" at 9698.44,977.81 h82.24
  text "02" at 3746.76,971.5 h82.24
  text "LAYER 2 & 3 (INNER LAYERS) XX MIL WIDE, XX MIL SPACE / TRACES REQUIRE 100 OHM DIFFERENTIAL IMPEDANCE" at 11584.52,899.78 h60
  text "L02,L07" at 10662.95,840.17 h82.24
  text "EDGE COUPLED MICROSTRIP" at 4033.7,836.99 h82.24
  text "L1,L8" at 6083.27,837.06 h82.24
  text "5.1" at 7231.18,833.89 h82.24
  text "100" at 9698.44,833.89 h82.24
  text "8.6" at 8482.68,831.82 h82.24
  text "03" at 3746.76,827.58 h82.24
  text "L03" at 10662.95,696.25 h82.24
  text "EDGE COUPLED MICROSTRIP" at 4033.7,693.06 h82.24
  text "L1" at 6083.27,693.14 h82.24
  text "5.2" at 7231.18,689.96 h82.24
  text "120" at 9698.44,689.96 h82.24
  text "7.15" at 8464.64,687.5 h82.24
  text "04" at 3746.76,683.66 h82.24
  text "L02/04,L05/07" at 10394.06,559.08 h82.24
  text "STRIPLINE" at 4029.49,554.53 h82.24
  text "L3,L6" at 6086.6,553 h82.24
  text "5.947" at 7231.18,545.16 h82.24
  text "---" at 8485.37,545.16 h82.24
  text "50" at 9698.44,545.16 h82.24
  text "05" at 3746.76,539.73 h82.24
  text "100" at 9655.71,413.87 h82.24
  text "L3" at 6085.27,409.43 h82.24
  text "L02/04" at 10530.07,401.67 h82.24
  text "06" at 3756.63,399.12 h82.24
  text "EDGE COUPLED STRIPLINE" at 4056.33,399.12 h82.24
  text "4.8" at 7234.8,398.33 h82.24
  text "11.2" at 8528.4,394.58 h82.24
  text "PROJECT TITLE:" at 11343.5,277.5 h45
  text "50" at 9664.81,268.27 h82.24
  text "L1" at 6091.82,265.38 h82.24
  text "L03" at 10674.84,263.63 h82.24
  text "5" at 8552.45,262.3 h82.24
  text "COPLANAR" at 4095.42,249.27 h82.24
  text "12" at 7240.78,248.77 h82.24
  text "07" at 3746.86,242.75 h82.24
  text ".PRJ_Title" at 11393.5,144.17 h70
  text "DESIGNED FOR:" at 11343.5,-23.5 h45
  text ".PRJ_Customer" at 11393.5,-163.5 h70
  text "D" at -416.5,-231.5 h70
  text "D" at 14383.5,-231.5 h70
  text "FILE NAME:" at 11343.5,-323.5 h45
  text ".PCB_File_Name_No_Path" at 11393.5,-443.5 h70
  text "Texas Instruments (TI) and/or its licensors do not warrant the accuracy or completeness of this specification" at 6374,-605.34 h45
  text "ENGINEER:" at 11343.5,-613.5 h45
  text "LAYOUT BY:" at 12848.5,-613.5 h45
  text "or any information contained therein. TI and/or its licensors do not warrant that this design will meet" at 6329.01,-718 h45
  text ".PRJ_Engineer" at 11393.5,-768.49 h70
  text ".PCB_Layout" at 12899,-768.49 h70
  text "the specifications, will be suitable for your application or fit for any particular purpose, or will operate in" at 6329.01,-830.67 h45
  text ".Layer_Name" at 577,-858.49 h60
  text "ALTIUM DESIGNER VERSION:" at 12848.5,-923.5 h45
  text "an implementation. TI and/or its licensors do not warrant that the design is production worthy. You should" at 6329.01,-943.33 h45
  text "completely validate and test your design implementation to confirm the system functionality for your application." at 6374,-1056 h45
  text ".print_Scale" at 11393.5,-1056.83 h70
  text ".Application_BuildNumber" at 12899,-1056.83 h70
  text "1" at 739.84,-1263.5 h70
  text "2" at 3235.5,-1263.5 h70
  text "3" at 5724.84,-1263.5 h70
  text "4" at 8231.51,-1263.5 h70
  text "5" at 10730.5,-1263.5 h70
  text "6" at 13235.5,-1263.5 h70
M11 Gerber Information:
  lines w10: -288.5,-917.67 6311.5,-917.67 ; -288.5,-714.33 6313.5,-714.33 ; -288.5,-511 -288.5,-1121 3716.5,-1121 6313.5,-1121 6313.5,-511 -288,-511 -288,-1121 1287.5,-1121 ; 2176.5,-1121 2176.5,-511 ; 3443.5,-714.33 3443.5,-511 ; 4283.5,-714.33 4283.5,-511 ; 4905.5,-1127.5 4905.5,-924.67
  text "ALL ARTWORK VIEWED FROM TOP SIDE" at -228.5,-655.67 h60
  text "BOARD #:" at 2248,-655.67 h60
  text ".PRJ_Number" at 2793.5,-655.67 h60
  text "REV:" at 3638,-655.67 h60
  text ".PCB_Rev" at 3929.5,-655.67 h60
  text "SVN REV:" at 4476,-655.67 h60
  text ".VersionControl_RevNumber" at 4982,-655.67 h60
  text "LAYER NAME =" at -228.5,-858.49 h60
  text "TID #:" at 2248,-859 h60
  text ".TID" at 2793.5,-859 h60
  text "PLOT NAME =" at -228.5,-1064.34 h60
  text ".plot_File_Name" at 577,-1064.34 h60
  text "GENERATED    :" at 2250,-1064.34 h60
  text ".Print_Date" at 3119.5,-1064.34 h60
  text ".Print_Time" at 3848.5,-1064.34 h60
  text "TEXAS INSTRUMENTS" at 5113,-1064.34 h60
M12 Stackup:
  drawing of 607 lines, arcs and shapes, not listed
  text "Layer" at -154.44,1763.05 h49.01
  text "Name" at 184.03,1763.05 h49.01
  text "Material" at 947.09,1763.05 h49.01
  text "Thickness" at 1653,1763.05 h49.01
  text "Constant" at 2187.44,1763.05 h49.01
  text "Board Layer Stack" at 2656.55,1763.05 h49.01
  text "1" at -154.44,1665.03 h49.01
  text "Top Overlay" at 184.03,1665.03 h49.01
  text "2" at -154.44,1567.02 h49.01
  text "Top Solder" at 184.03,1567.02 h49.01
  text "Solder Resist" at 947.09,1567.02 h49.01
  text "2.00mil" at 1653,1567.02 h49.01
  text "3.9" at 2187.44,1567.02 h49.01
  text "3" at -154.44,1469 h49.01
  text "Top Layer" at 184.03,1469 h49.01
  text "Copper" at 947.09,1469 h49.01
  text "2.76mil" at 1653,1469 h49.01
  text "4" at -154.44,1370.99 h49.01
  text "Dielectric1" at 184.03,1370.99 h49.01
  text "PP-006" at 947.09,1370.99 h49.01
  text "1.68mil" at 1653,1370.99 h49.01
  text "3.79" at 2187.44,1370.99 h49.01
  text "5" at -154.44,1272.98 h49.01
  text "Dielectric 1" at 184.03,1272.98 h49.01
  text "PP-006" at 947.09,1272.98 h49.01
  text "2.56mil" at 1653,1272.98 h49.01
  text "3.86" at 2187.44,1272.98 h49.01
  text "6" at -154.44,1174.96 h49.01
  text "GND1" at 184.03,1174.96 h49.01
  text "Copper" at 947.09,1174.96 h49.01
  text "2.64mil" at 1653,1174.96 h49.01
  text "7" at -154.44,1076.95 h49.01
  text "Dielectric3" at 184.03,1076.95 h49.01
  text "Core-009" at 947.09,1076.95 h49.01
  text "12.00mil" at 1653,1076.95 h49.01
  text "4.47" at 2187.44,1076.95 h49.01
  text "8" at -154.44,978.94 h49.01
  text "Sig1" at 184.03,978.94 h49.01
  text "Copper" at 947.09,978.94 h49.01
  text "2.64mil" at 1653,978.94 h49.01
  text "9" at -154.44,880.92 h49.01
  text "Dielectric2" at 184.03,880.92 h49.01
  text "PP-006" at 947.09,880.92 h49.01
  text "2.70mil" at 1653,880.92 h49.01
  text "4.13" at 2187.44,880.92 h49.01
  text "10" at -154.44,782.91 h49.01
  text "Dielectric 3" at 184.03,782.91 h49.01
  text "PP-006" at 947.09,782.91 h49.01
  text "2.70mil" at 1653,782.91 h49.01
  text "4.13" at 2187.44,782.91 h49.01
  text "11" at -154.44,684.89 h49.01
  text "PWR1" at 184.03,684.89 h49.01
  text "Copper" at 947.09,684.89 h49.01
  text "2.64mil" at 1653,684.89 h49.01
  text "12" at -154.44,586.88 h49.01
  text "Dielectric4" at 184.03,586.88 h49.01
  text "Core-009" at 947.09,586.88 h49.01
  text "5.00mil" at 1653,586.88 h49.01
  text "4.21" at 2187.44,586.88 h49.01
  text "13" at -154.44,488.87 h49.01
  text "PWR2" at 184.03,488.87 h49.01
  text "Copper" at 947.09,488.87 h49.01
  text "2.64mil" at 1653,488.87 h49.01
  text "14" at -154.44,390.85 h49.01
  text "Dielectric5" at 184.03,390.85 h49.01
  text "PP-006" at 947.09,390.85 h49.01
  text "2.70mil" at 1653,390.85 h49.01
  text "4.13" at 2187.44,390.85 h49.01
  text "15" at -154.44,292.84 h49.01
  text "Dielectric 4" at 184.03,292.84 h49.01
  text "PP-006" at 947.09,292.84 h49.01
  text "2.70mil" at 1653,292.84 h49.01
  text "4.13" at 2187.44,292.84 h49.01
  text "16" at -154.44,194.83 h49.01
  text "Sig2" at 184.03,194.83 h49.01
  text "Copper" at 947.09,194.83 h49.01
  text "2.64mil" at 1653,194.83 h49.01
  text "17" at -154.44,96.81 h49.01
  text "Dielectric8" at 184.03,96.81 h49.01
  text "Core-009" at 947.09,96.81 h49.01
  text "12.00mil" at 1653,96.81 h49.01
  text "4.47" at 2187.44,96.81 h49.01
  text "18" at -154.44,-1.2 h49.01
  text "GND2" at 184.03,-1.2 h49.01
  text "Copper" at 947.09,-1.2 h49.01
  text "2.64mil" at 1653,-1.2 h49.01
  text "19" at -154.44,-99.22 h49.01
  text "Dielectric9" at 184.03,-99.22 h49.01
  text "PP-006" at 947.09,-99.22 h49.01
  text "2.56mil" at 1653,-99.22 h49.01
  text "3.86" at 2187.44,-99.22 h49.01
  text "20" at -154.44,-197.23 h49.01
  text "Dielectric 2" at 184.03,-197.23 h49.01
  text "PP-006" at 947.09,-197.23 h49.01
  text "1.68mil" at 1653,-197.23 h49.01
  text "3.79" at 2187.44,-197.23 h49.01
  text "21" at -154.44,-295.24 h49.01
  text "Bottom Layer" at 184.03,-295.24 h49.01
  text "Copper" at 947.09,-295.24 h49.01
  text "2.76mil" at 1653,-295.24 h49.01
  text "22" at -154.44,-393.26 h49.01
  text "Bottom Solder" at 184.03,-393.26 h49.01
  text "Solder Resist" at 947.09,-393.26 h49.01
  text "2.00mil" at 1653,-393.26 h49.01
  text "3.9" at 2187.44,-393.26 h49.01
  text "23" at -154.44,-491.27 h49.01
  text "Bottom Overlay" at 184.03,-491.27 h49.01
  text ".Layer_Name" at 577,-858.49 h60
M13 Component Bodies Top:
  text ".Layer_Name" at 577,-858.49 h60
M14 Component Bodies Bottom:
  text ".Layer_Name" at 577,-858.49 h60
M15 Courtyards Top:
  text ".Layer_Name" at 577,-858.49 h60
M16 Courtyards Bottom:
  text ".Layer_Name" at 577,-858.49 h60
Drill Drawing:
  drawing of 183 lines, arcs and shapes, not listed
  text "Symbol" at -171.23,7847.68 h72
  text "Count" at 334.65,7847.68 h72
  text "Hole Size" at 924.49,7847.68 h72
  text "Plated" at 2074.15,7847.68 h72
  text "Hole Tolerance (+)" at 2580.03,7847.68 h72
  text "Hole Tolerance (-)" at 3913.64,7847.68 h72
  text "35" at 334.65,7697.68 h60
  text "7.87mil (0.200mm)" at 924.49,7697.68 h60
  text "PTH" at 2074.15,7697.68 h60
  text "752" at 334.65,7547.68 h60
  text "8.00mil (0.203mm)" at 924.49,7547.68 h60
  text "PTH" at 2074.15,7547.68 h60
  text "53" at 334.65,7397.68 h60
  text "8.00mil (0.203mm)" at 924.49,7397.68 h60
  text "PTH" at 2074.15,7397.68 h60
  text "3.00mil (0.076mm)" at 2580.03,7397.68 h60
  text "3.00mil (0.076mm)" at 3913.64,7397.68 h60
  text "3" at 334.65,7247.68 h60
  text "10.00mil (0.254mm)" at 924.49,7247.68 h60
  text "PTH" at 2074.15,7247.68 h60
  text "3.00mil (0.076mm)" at 2580.03,7247.68 h60
  text "3.00mil (0.076mm)" at 3913.64,7247.68 h60
  text "10" at 334.65,7097.68 h60
  text "23.62mil (0.600mm)" at 924.49,7097.68 h60
  text "PTH" at 2074.15,7097.68 h60
  text "2" at 334.65,6947.68 h60
  text "23.62mil (0.600mm)" at 924.49,6947.68 h60
  text "PTH" at 2074.15,6947.68 h60
  text "10" at 334.65,6797.68 h60
  text "27.56mil (0.700mm)" at 924.49,6797.68 h60
  text "PTH" at 2074.15,6797.68 h60
  text "3" at 334.65,6647.68 h60
  text "31.50mil (0.800mm)" at 924.49,6647.68 h60
  text "PTH" at 2074.15,6647.68 h60
  text "3.94mil (0.100mm)" at 2580.03,6647.68 h60
  text "3.94mil (0.100mm)" at 3913.64,6647.68 h60
  text "A" at -200.32,6637.69 h66.67
  text "2" at 334.65,6497.68 h60
  text "31.50mil (0.800mm)" at 924.49,6497.68 h60
  text "PTH" at 2074.15,6497.68 h60
  text "3.94mil (0.100mm)" at 2580.03,6497.68 h60
  text "3.94mil (0.100mm)" at 3913.64,6497.68 h60
  text "2" at 334.65,6347.68 h60
  text "33.47mil (0.850mm)" at 924.49,6347.68 h60
  text "PTH" at 2074.15,6347.68 h60
  text "1" at 334.65,6197.68 h60
  text "40.00mil (1.016mm)" at 924.49,6197.68 h60
  text "PTH" at 2074.15,6197.68 h60
  text "1" at 334.65,6047.68 h60
  text "64.96mil (1.650mm)" at 924.49,6047.68 h60
  text "PTH" at 2074.15,6047.68 h60
  text "55" at 334.65,5897.68 h60
  text "24.00mil (0.610mm)" at 924.49,5897.68 h60
  text "NPTH" at 2074.15,5897.68 h60
  text "3.00mil (0.076mm)" at 2580.03,5897.68 h60
  text "3.00mil (0.076mm)" at 3913.64,5897.68 h60
  text "4" at 334.65,5747.68 h60
  text "40.16mil (1.020mm)" at 924.49,5747.68 h60
  text "NPTH" at 2074.15,5747.68 h60
  text "6" at 334.65,5597.68 h60
  text "88.00mil (2.235mm)" at 924.49,5597.68 h60
  text "NPTH" at 2074.15,5597.68 h60
  text "3.00mil (0.076mm)" at 2580.03,5597.68 h60
  text "3.00mil (0.076mm)" at 3913.64,5597.68 h60
  text "2" at 334.65,5447.68 h60
  text "100.00mil (2.540mm)" at 924.49,5447.68 h60
  text "NPTH" at 2074.15,5447.68 h60
  text "3.00mil (0.076mm)" at 2580.03,5447.68 h60
  text "3.00mil (0.076mm)" at 3913.64,5447.68 h60
  text "941 Total" at 334.65,5297.68 h60
  text "Slot definitions :" at -171.23,5152.71 h60
  text "Routed Path Length" at 861.46,5152.71 h60
  text "= Calculated from tool start centre position to tool end centre position." at 1964.13,5152.71 h60
  text "Hole Length" at 861.46,5052.73 h60
  text "= Routed Path Length + Tool Size = Slot length as defined in the PCB layout" at 1554.26,5052.73 h60
  text ".Layer_Name" at 577,-858.49 h60
M17 Embedded Cavity:
  text ".Layer_Name" at 577,-858.49 h60
M18 Embedded Assembly:
  text ".Layer_Name" at 577,-858.49 h60
M19 Embedded Keepout:
  text ".Layer_Name" at 577,-858.49 h60
Mechanical 21:
  drawing of 1383 lines, arcs and shapes, not listed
